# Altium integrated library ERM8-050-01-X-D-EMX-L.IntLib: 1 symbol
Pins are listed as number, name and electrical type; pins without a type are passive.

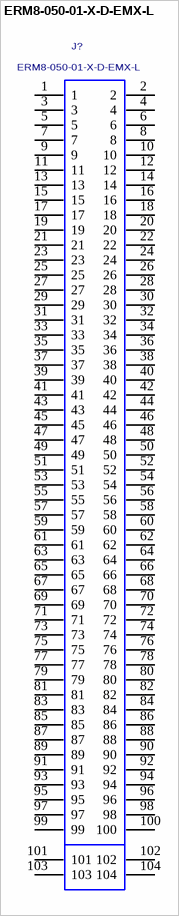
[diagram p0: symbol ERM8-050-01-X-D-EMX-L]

## ERM8-050-01-X-D-EMX-L
designator J?
Edge Rate, Contract Skt Strip Male, .8 mm Pitch, 100 Pins.; MANUFACTURER: SAMTEC
footprint ERM8-050-01-X-D-EMX-L
pins: 1, 2, 3, 4, 5, 6, 7, 8, 9, 10, 11, 12, 13, 14, 15, 16, 17, 18, 19, 20, 21, 22, 23, 24, 25, 26, 27, 28, 29, 30, 31, 32, 33, 34, 35, 36, 37, 38, 39, 40, 41, 42, 43, 44, 45, 46, 47, 48, 49, 50, 51, 52, 53, 54, 55, 56, 57, 58, 59, 60, 61, 62, 63, 64, 65, 66, 67, 68, 69, 70, 71, 72, 73, 74, 75, 76, 77, 78, 79, 80, 81, 82, 83, 84, 85, 86, 87, 88, 89, 90, 91, 92, 93, 94, 95, 96, 97, 98, 99, 100, 101, 102, 103, 104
